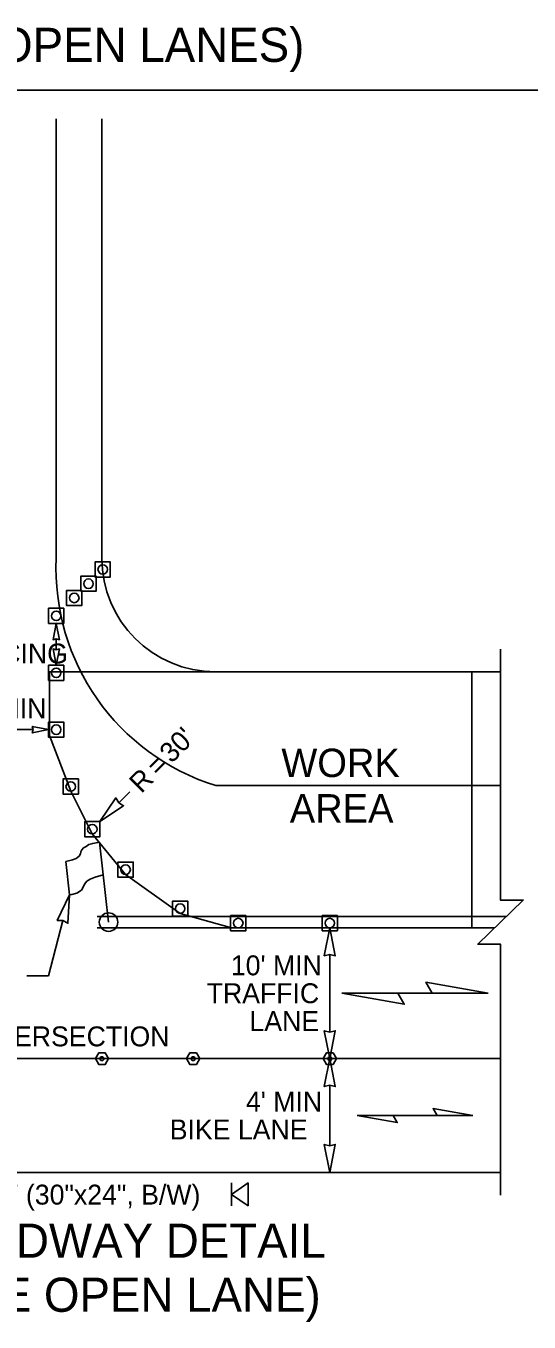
# Model space of a CAD drawing. Extents: x 99998.9 to 100095.7, y 99995 to 100010.7.
# Drawn here: x 100068.609 to 100070.375, y 100001.65 to 100006.207 of the extents above; entities that cross this region are included whole.
import ezdxf

# ---------------------------------------------------------------- set-up
doc = ezdxf.new("R2010")
doc.units = 0
for name, color, linetype in [('RD_ED_ShoulderPavedEdge', 7, 'Continuous'), ('RD_MK_LineDblYellowCenter', 7, 'Continuous'), ('RD_MK_LineEdgeWhite', 7, 'Continuous'), ('SH_DE_DetailHeading2Text', 7, 'Continuous'), ('TR_WZ_FlaggingStation', 7, 'Continuous'), ('TR_WZ_PortableSignMountBlk-Wht', 7, 'Continuous'), ('TR_WZ_TrafficCone', 7, 'Continuous'), ('TR_WZ_TubularMarker', 7, 'Continuous'), ('TR_WZ_WorkAreaLabel', 7, 'Continuous'), ('TR_WZ_WorkZoneDetails', 7, 'Continuous'), ('TR_WZ_WorkZoneTextCurrent', 7, 'Continuous')]:
    doc.layers.add(name, color=color, linetype=linetype)

msp = doc.modelspace()

# ---------------------------------------------------------------- linework, layer by layer
at = {"layer": 'RD_ED_ShoulderPavedEdge'}
for p, q in [((100069.275, 100003.9359), (100070.275, 100003.9359)), ((100065.475, 100002.1759), (100070.275, 100002.1759))]:
    msp.add_line(p, q, dxfattribs=at)
msp.add_lwpolyline([(100068.875, 100005.8804), (100068.875, 100004.3359)], dxfattribs=at)
msp.add_arc((100069.275, 100004.3359), 0.4, 180, 270, dxfattribs=at)
at = {"layer": 'RD_MK_LineDblYellowCenter'}
for p, q in [((100068.8588, 100003.0759), (100070.2957, 100003.0759)), ((100068.8588, 100003.0359), (100070.2543, 100003.0359))]:
    msp.add_line(p, q, dxfattribs=at)
at = {"layer": 'RD_MK_LineEdgeWhite'}
for p, q in [((100068.715, 100004.3359), (100068.715, 100005.8804)), ((100069.275, 100003.5359), (100070.275, 100003.5359)), ((100065.475, 100002.5759), (100070.275, 100002.5759))]:
    msp.add_line(p, q, dxfattribs=at)
msp.add_arc((100069.5142, 100004.2993), 0.8, 177.3788, 252.6052, dxfattribs=at)
at = {"layer": 'TR_WZ_FlaggingStation'}
for p, q in [((100068.8797, 100003.2228), (100068.8667, 100003.3371)), ((100068.8988, 100003.0559), (100068.8667, 100003.3368)), ((100068.7487, 100003.2693), (100068.762, 100003.1521)), ((100068.8797, 100003.2228), (100068.8797, 100003.2228))]:
    msp.add_line(p, q, dxfattribs=at)
for points in [[(100068.8667, 100003.3371), (100068.8609, 100003.3359), (100068.8431, 100003.3324), (100068.8293, 100003.3283), (100068.8196, 100003.3222), (100068.8111, 100003.3175), (100068.8054, 100003.3106), (100068.8012, 100003.3028), (100068.8006, 100003.2966), (100068.7953, 100003.2874), (100068.7845, 100003.2799), (100068.7721, 100003.2747), (100068.7487, 100003.2693)], [(100068.762, 100003.1521), (100068.7702, 100003.1536), (100068.7879, 100003.1582), (100068.8035, 100003.1687), (100068.81, 100003.1793), (100068.814, 100003.1896), (100068.823, 100003.2005), (100068.834, 100003.2067), (100068.8514, 100003.2138), (100068.8797, 100003.2228)]]:
    msp.add_lwpolyline(points, dxfattribs=at)
msp.add_circle((100068.8988, 100003.0559), 0.0325, dxfattribs=at)
at = {"layer": 'TR_WZ_PortableSignMountBlk-Wht'}
msp.add_line((100069.331, 100002.059), (100069.331, 100002.139), dxfattribs=at)
msp.add_lwpolyline([(100069.331, 100002.0989), (100069.3885, 100002.139), (100069.3885, 100002.059)], close=True, dxfattribs=at)
at = {"layer": 'TR_WZ_TrafficCone'}
for points in [[(100068.8516, 100004.3224), (100068.8516, 100004.2691), (100068.9049, 100004.2691), (100068.9049, 100004.3224), (100068.8516, 100004.3224)], [(100068.9049, 100004.3224), (100068.9049, 100004.2691), (100068.8516, 100004.2691), (100068.8516, 100004.3224), (100068.9049, 100004.3224)], [(100068.8016, 100004.2724), (100068.8016, 100004.2191), (100068.8549, 100004.2191), (100068.8549, 100004.2724), (100068.8016, 100004.2724)], [(100068.8549, 100004.2724), (100068.8549, 100004.2191), (100068.8016, 100004.2191), (100068.8016, 100004.2724), (100068.8549, 100004.2724)], [(100068.7516, 100004.2224), (100068.7516, 100004.1691), (100068.8049, 100004.1691), (100068.8049, 100004.2224), (100068.7516, 100004.2224)], [(100068.8049, 100004.2224), (100068.8049, 100004.1691), (100068.7516, 100004.1691), (100068.7516, 100004.2224), (100068.8049, 100004.2224)], [(100068.7416, 100004.1592), (100068.6883, 100004.1592), (100068.6883, 100004.1059), (100068.7416, 100004.1059), (100068.7416, 100004.1592)], [(100068.7416, 100004.1059), (100068.6883, 100004.1059), (100068.6883, 100004.1592), (100068.7416, 100004.1592), (100068.7416, 100004.1059)], [(100068.7416, 100003.9592), (100068.6883, 100003.9592), (100068.6883, 100003.9059), (100068.7416, 100003.9059), (100068.7416, 100003.9592)], [(100068.7416, 100003.9059), (100068.6883, 100003.9059), (100068.6883, 100003.9592), (100068.7416, 100003.9592), (100068.7416, 100003.9059)], [(100068.7416, 100003.7592), (100068.6883, 100003.7592), (100068.6883, 100003.7059), (100068.7416, 100003.7059), (100068.7416, 100003.7592)], [(100068.7416, 100003.7059), (100068.6883, 100003.7059), (100068.6883, 100003.7592), (100068.7416, 100003.7592), (100068.7416, 100003.7059)], [(100068.7927, 100003.5592), (100068.7393, 100003.5592), (100068.7393, 100003.5059), (100068.7927, 100003.5059), (100068.7927, 100003.5592)], [(100068.7927, 100003.5059), (100068.7393, 100003.5059), (100068.7393, 100003.5592), (100068.7927, 100003.5592), (100068.7927, 100003.5059)], [(100068.8683, 100003.4093), (100068.815, 100003.4093), (100068.815, 100003.3559), (100068.8683, 100003.3559), (100068.8683, 100003.4093)], [(100068.8683, 100003.3559), (100068.815, 100003.3559), (100068.815, 100003.4093), (100068.8683, 100003.4093), (100068.8683, 100003.3559)], [(100068.9853, 100003.267), (100068.9319, 100003.267), (100068.9319, 100003.2136), (100068.9853, 100003.2136), (100068.9853, 100003.267)], [(100068.9853, 100003.2136), (100068.9319, 100003.2136), (100068.9319, 100003.267), (100068.9853, 100003.267), (100068.9853, 100003.2136)], [(100069.177, 100003.1302), (100069.1236, 100003.1302), (100069.1236, 100003.0768), (100069.177, 100003.0768), (100069.177, 100003.1302)], [(100069.177, 100003.0768), (100069.1236, 100003.0768), (100069.1236, 100003.1302), (100069.177, 100003.1302), (100069.177, 100003.0768)], [(100069.381, 100003.0792), (100069.3276, 100003.0792), (100069.3276, 100003.0259), (100069.381, 100003.0259), (100069.381, 100003.0792)], [(100069.381, 100003.0259), (100069.3276, 100003.0259), (100069.3276, 100003.0792), (100069.381, 100003.0792), (100069.381, 100003.0259)], [(100069.649, 100003.0792), (100069.7024, 100003.0792), (100069.7024, 100003.0259), (100069.649, 100003.0259), (100069.649, 100003.0792)], [(100069.649, 100003.0259), (100069.7024, 100003.0259), (100069.7024, 100003.0792), (100069.649, 100003.0792), (100069.649, 100003.0259)]]:
    msp.add_lwpolyline(points, dxfattribs=at)
for centre in [(100068.8783, 100004.2958), (100068.8283, 100004.2458), (100068.7783, 100004.1958), (100068.715, 100004.1326), (100068.715, 100003.9326), (100068.715, 100003.7326), (100068.766, 100003.5326), (100068.8417, 100003.3826), (100068.9586, 100003.2403), (100069.1503, 100003.1035), (100069.3543, 100003.0526), (100069.6757, 100003.0526)]:
    msp.add_circle(centre, 0.0167, dxfattribs=at)
at = {"layer": 'TR_WZ_TubularMarker'}
for points in [[(100068.8526, 100002.5759), (100068.8641, 100002.5959), (100068.8872, 100002.5959), (100068.8988, 100002.5759), (100068.8872, 100002.5559), (100068.8641, 100002.5559)], [(100069.1726, 100002.5759), (100069.1841, 100002.5959), (100069.2072, 100002.5959), (100069.2188, 100002.5759), (100069.2072, 100002.5559), (100069.1841, 100002.5559)], [(100069.6526, 100002.5759), (100069.6641, 100002.5959), (100069.6872, 100002.5959), (100069.6988, 100002.5759), (100069.6872, 100002.5559), (100069.6641, 100002.5559)]]:
    msp.add_lwpolyline(points, close=True, dxfattribs=at)
for points in [[(100068.8641, 100002.5559), (100068.8872, 100002.5559), (100068.8988, 100002.5759), (100068.8872, 100002.5959), (100068.8641, 100002.5959), (100068.8526, 100002.5759), (100068.8641, 100002.5559)], [(100069.1841, 100002.5559), (100069.2072, 100002.5559), (100069.2188, 100002.5759), (100069.2072, 100002.5959), (100069.1841, 100002.5959), (100069.1726, 100002.5759), (100069.1841, 100002.5559)], [(100069.6641, 100002.5559), (100069.6872, 100002.5559), (100069.6988, 100002.5759), (100069.6872, 100002.5959), (100069.6641, 100002.5959), (100069.6526, 100002.5759), (100069.6641, 100002.5559)]]:
    msp.add_lwpolyline(points, dxfattribs=at)
for centre in [(100068.8757, 100002.5759), (100069.1957, 100002.5759), (100069.6757, 100002.5759)]:
    msp.add_circle(centre, 0.00667, dxfattribs=at)
at = {"layer": 'TR_WZ_WorkZoneDetails'}
for p, q in [((100070.5, 100005.9804), (100065.25, 100005.9804)), ((100068.715, 100004.0514), (100068.715, 100004.0137)), ((100068.6338, 100003.7326), (100068.3962, 100003.7326)), ((100068.9346, 100003.4755), (100068.973, 100003.514)), ((100068.7385, 100003.0614), (100068.688, 100002.8668)), ((100069.6756, 100002.6696), (100069.6756, 100002.9422)), ((100068.6118, 100002.8668), (100068.688, 100002.8668)), ((100070.0356, 100002.8059), (100069.7945, 100002.8059)), ((100069.9151, 100002.8059), (100070.1562, 100002.8059)), ((100069.6756, 100002.2696), (100069.6756, 100002.4822)), ((100070.0525, 100002.3759), (100069.8982, 100002.3759)), ((100069.8982, 100002.3759), (100070.0525, 100002.3759))]:
    msp.add_line(p, q, dxfattribs=at)
for points in [[(100068.715, 100004.1059), (100068.7262, 100004.0487), (100068.715, 100004.0514), (100068.7037, 100004.0487)], [(100068.715, 100003.9592), (100068.7262, 100004.0164), (100068.715, 100004.0137), (100068.7038, 100004.0164)], [(100070.175, 100003.9359), (100070.175, 100003.0359), (100069.699, 100003.0359), (100069.6523, 100003.0359), (100069.6523, 100003.0359), (100069.6523, 100003.0359), (100069.331, 100003.0359), (100069.331, 100003.0359), (100069.331, 100003.0359), (100069.1503, 100003.0868), (100068.9586, 100003.2236), (100068.8417, 100003.3659), (100068.766, 100003.5159), (100068.6917, 100003.7126), (100068.6917, 100003.9359)], [(100068.6883, 100003.7326), (100068.6311, 100003.7214), (100068.6338, 100003.7326), (100068.6311, 100003.7438)], [(100068.8683, 100003.4093), (100068.9514, 100003.4652), (100068.9346, 100003.4756), (100068.9242, 100003.4924)], [(100068.762, 100003.1521), (100068.7187, 100003.0618), (100068.7385, 100003.0614), (100068.7561, 100003.0522)], [(100069.6757, 100003.0359), (100069.6564, 100002.9376), (100069.6757, 100002.9422), (100069.695, 100002.9376)], [(100070.2321, 100002.8059), (100070.0133, 100002.8445), (100070.0356, 100002.8059)], [(100069.7185, 100002.8059), (100069.9373, 100002.7673), (100069.9151, 100002.8059)], [(100069.6756, 100002.5759), (100069.6564, 100002.6742), (100069.6756, 100002.6696), (100069.6949, 100002.6742)], [(100069.6756, 100002.5759), (100069.6564, 100002.4776), (100069.6756, 100002.4822), (100069.6949, 100002.4776)], [(100069.7724, 100002.3759), (100069.9124, 100002.3512), (100069.8982, 100002.3759)], [(100070.1783, 100002.3759), (100070.0382, 100002.4006), (100070.0525, 100002.3759)], [(100069.6756, 100002.1759), (100069.6564, 100002.2742), (100069.6756, 100002.2696), (100069.6949, 100002.2742)]]:
    msp.add_lwpolyline(points, close=True, dxfattribs=at)
msp.add_lwpolyline([(100070.275, 100002.0959), (100070.275, 100002.9785), (100070.195, 100002.9785), (100070.355, 100003.1333), (100070.275, 100003.1333), (100070.275, 100004.0159)], dxfattribs=at)

# ---------------------------------------------------------------- texts
at = {"layer": 'SH_DE_DetailHeading2Text'}
for s, p in [('SAME SIDE AS LANE CLOSURE (TWO OPEN LANES)', (100065.5738, 100006.0804)), ('UNSIGNALIZED INTERSECTING ROADWAY DETAIL', (100065.7563, 100001.8759)), ('SAME SIDE AS LANE CLOSURE (SINGLE OPEN LANE)', (100065.524, 100001.6859))]:
    msp.add_text(s, height=0.12, rotation=360, dxfattribs=at).set_placement(p)
at = {"layer": 'TR_WZ_WorkAreaLabel'}
for s, p in [('WORK', (100069.5056, 100003.5659)), ('AREA', (100069.5352, 100003.4059))]:
    msp.add_text(s, height=0.1, dxfattribs=at).set_placement(p)
at = {"layer": 'TR_WZ_WorkZoneDetails'}
msp.add_text('R3-17 (30"x24", B/W)', height=0.07, rotation=360, dxfattribs=at).set_placement((100068.3277, 100002.0629))
at = {"layer": 'TR_WZ_WorkZoneTextCurrent'}
for s, p in [('SPACING', (100068.3346, 100003.9654)), ("10' MIN", (100068.3608, 100003.7726)), ("10' MIN", (100069.3283, 100002.8689)), ('TRAFFIC', (100069.2433, 100002.7709)), ('LANE', (100069.3937, 100002.6729)), ("10' SPACING ACROSS INTERSECTION", (100067.3993, 100002.6192)), ("4' MIN", (100069.3812, 100002.3899)), ('BIKE LANE', (100069.1137, 100002.2919))]:
    msp.add_text(s, height=0.07, dxfattribs=at).set_placement(p)
for s, p in [("30'", (100069.1202, 100003.6116)), ('=', (100069.0734, 100003.5648)), ('R', (100069.0142, 100003.5056))]:
    msp.add_text(s, height=0.07, rotation=45, dxfattribs=at).set_placement(p)

doc.saveas('drawing.dxf')
